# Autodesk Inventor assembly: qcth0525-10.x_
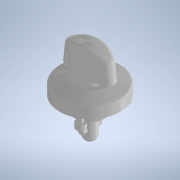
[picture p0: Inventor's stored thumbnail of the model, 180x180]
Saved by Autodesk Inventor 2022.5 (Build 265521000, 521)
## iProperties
Created: 2022-02
Part Number: qcth0525-10.x_
Document SubType Name: Assembly
Designer: ImaoCorp
Sending System: SOLIDWORKS 2020-2020296
MC: AMD64
MC_MODEL: Intel64 Family 6 Model 60 Stepping 3, GenuineIntel
OS: Windows_NT
FRU: Parasolid Version 31.1, build 290,  3- 9-2020
FORMAT: text
GUISE: transmit
KEY: qcth0525-10
FILE: qcth0525-10.x_t
DATE: Wed Feb 16 16:05:39 2022
Author: ImaoCorp
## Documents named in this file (6)
- X:\14_SW2022-Inv2022\00_全2023-1023新製品(TCC)まで\q\qcth0525-10\QCTH0525-10.iam
- X:\14_SW2022-Inv2022\00_全2023-1023新製品(TCC)まで\q\qcth0525-10\qcth0525-10_01.ipt
- X:\14_SW2022-Inv2022\00_全2023-1023新製品(TCC)まで\q\qcth0525-10\qcth0525-10_02.ipt
- X:\14_SW2022-Inv2022\00_全2023-1023新製品(TCC)まで\q\qcth0525-10\qcth0525-10_03.ipt
- X:\14_SW2022-Inv2022\00_全2023-1023新製品(TCC)まで\q\qcth0525-10\qcth0525-10_04.ipt
- X:\14_SW2022-Inv2022\00_全2023-1023新製品(TCC)まで\q\qcth0525-10\qcth0525-10_05.ipt
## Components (5 placed, 5 different names)
1. qcth0525-10_01
2. qcth0525-10_02
3. qcth0525-10_03
4. qcth0525-10_04
5. qcth0525-10_05
